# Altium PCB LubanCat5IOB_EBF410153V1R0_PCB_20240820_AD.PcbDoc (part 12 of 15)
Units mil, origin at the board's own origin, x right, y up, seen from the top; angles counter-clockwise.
Board outline 6811.02 x 4055.12 mil, 6 copper layers (TOP, GND02, ART03, ART04, PWR05, BOTTOM), stack 59.279 mil thick; 981 components, 783 nets, 3627 pads, 2669 vias.
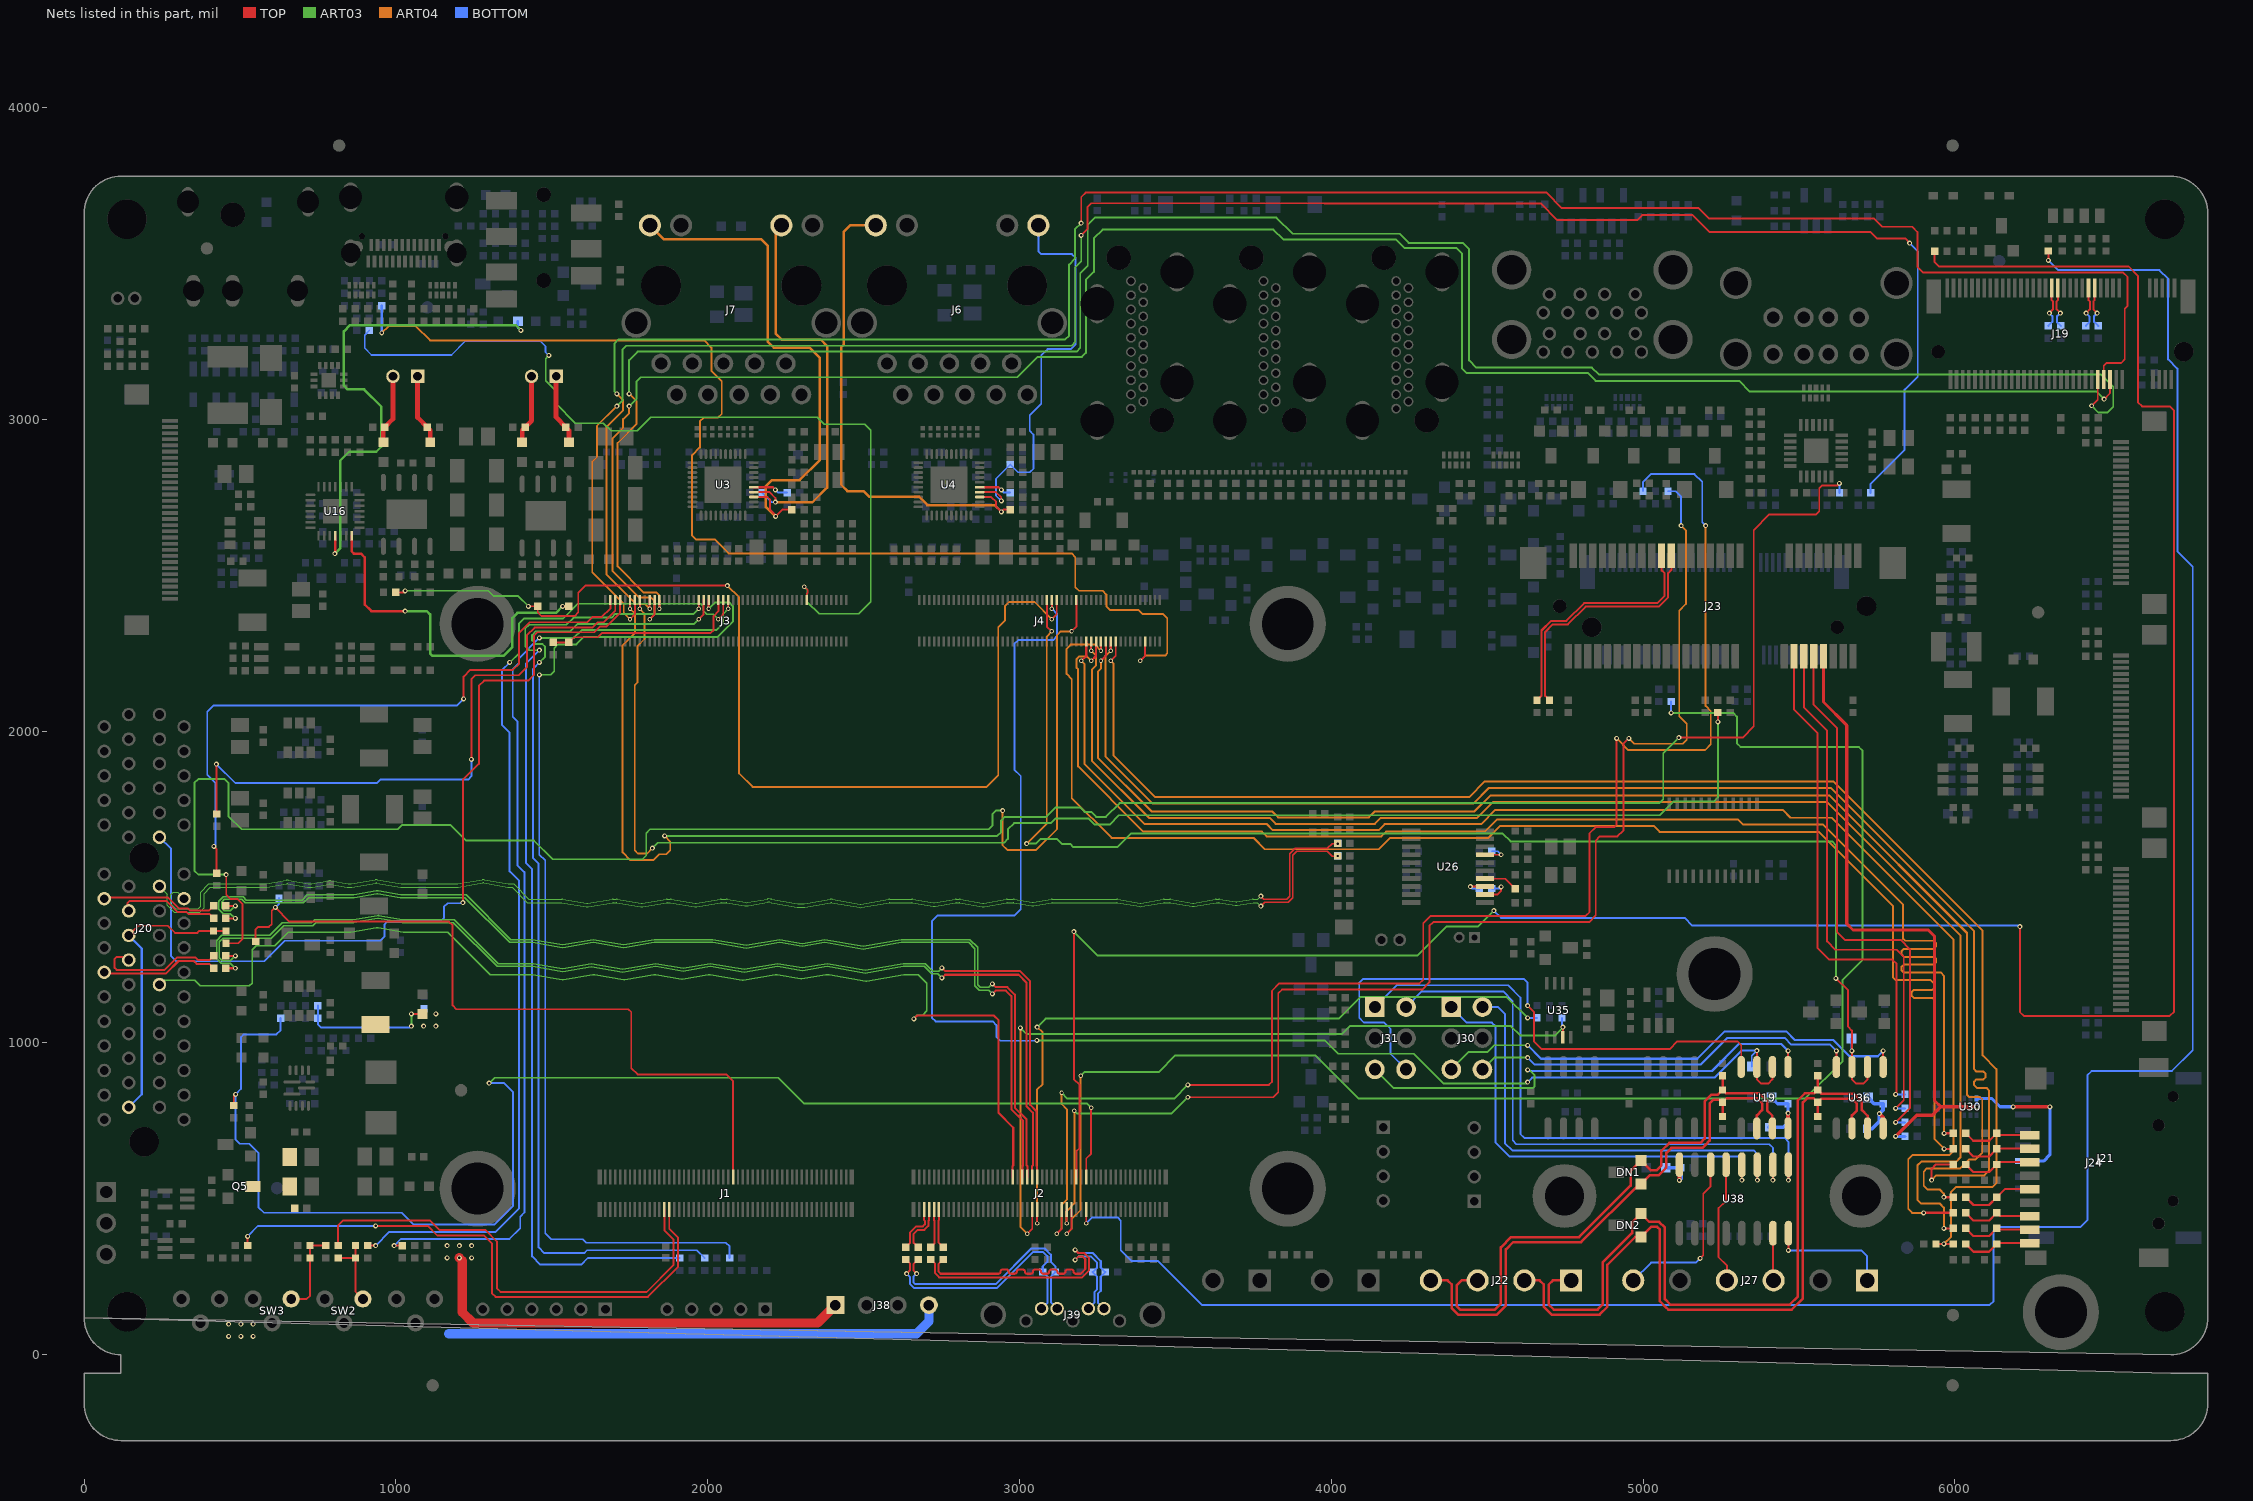
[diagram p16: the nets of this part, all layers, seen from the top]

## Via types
v1: diameter 16, hole 8, TOP to BOTTOM, 2357 vias
v2: diameter 14, hole 8, TOP to BOTTOM, 308 vias
v3: diameter 20, hole 10, TOP to BOTTOM, 4 vias

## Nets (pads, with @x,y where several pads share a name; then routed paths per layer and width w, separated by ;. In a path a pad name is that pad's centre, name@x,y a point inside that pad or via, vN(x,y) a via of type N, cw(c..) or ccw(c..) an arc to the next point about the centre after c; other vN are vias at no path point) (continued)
PCIE30_PORT1_RX1P: J2.39 J20.A21 | length 3642.6
  TOP w6.5: v1(2661,1077.14) 2671.36,1087.5 2918.24,1087.5 2933,1072.74 2933,775 2980.08,727.92 2980.08,606.42 2977.96,604.3 J2.39@2977.96,569.96
  ART03 w4.5: J20.A21@241.73,1187 254.88,1200.15 354.71,1200.15 371.87,1183 530,1183 539,1192 539,1298.67 552.33,1312 611,1312 654,1355 854.22,1355 ccw(c854.22,1364) 855.76,1355.13 936.88,1369.22 cw(c939.98,1351.38) 943.08,1369.22 1024.2,1355.13 ccw(c1025.74,1364) 1025.74,1355 1166,1355 1301.9,1219.1 1435.22,1219.1 cw(c1435.22,1201) 1438.32,1218.83 1533.63,1202.28 ccw(c1535.17,1211.15) 1536.71,1202.28 1632.01,1218.83 cw(c1635.11,1201) 1635.11,1219.1 cw(c1635.11,1201) 1638.21,1218.83 1731.12,1202.7 ccw(c1732.67,1211.62) 1734.22,1202.7 1827.13,1218.83 cw(c1830.22,1201) 1830.22,1219.1 cw(c1830.22,1201) 1833.32,1218.83 1916.18,1204.44 ccw(c1917.72,1213.31) 1919.26,1204.44 2002.12,1218.83 cw(c2005.22,1201) 2005.22,1219.1 cw(c2005.22,1201) 2008.32,1218.83 2111.17,1200.97 ccw(c2112.72,1209.89) 2114.27,1200.97 2217.13,1218.83 cw(c2220.23,1200.99) 2220.22,1219.1 cw(c2220.22,1201) 2223.32,1218.83 2299.22,1205.65 ccw(c2300.76,1214.52) 2302.3,1205.65 2378.2,1218.83 cw(c2381.29,1201) 2381.29,1219.1 2386.73,1219.1 cw(c2386.73,1201) 2389.83,1218.83 2507.61,1198.38 ccw(c2509.16,1207.3) 2510.7,1198.38 2628.47,1218.83 cw(c2631.57,1201) 2631.57,1219.1 2675.9,1219.1 2703.39,1191.61 2703.39,1103.03 2689.06,1088.7 2672.56,1088.7 v1(2661,1077.14)
PCIE30_PORT1_TX0N: C190.1 J2.45 | length 3522.9
  TOP w6.5: C190.1@454.68,1399.37 v1(485,1399.37) ; v1(2913,1189.36) 2923.36,1179 2961.26,1179 2985.5,1154.76 2985.5,791.76 3023.08,754.19 3023.08,606.42 3025.2,604.3 J2.45@3025.2,569.96
  ART03 w4.5: v1(485,1399.37) 469.55,1414.82 446.23,1414.82 431.9,1429.15 431.9,1454.77 446.23,1469.1 509.77,1469.1 520.77,1458.1 699.23,1458.1 716.13,1475 863.22,1475 ccw(c863.22,1484) 864.76,1475.13 937.35,1487.74 cw(c940.45,1469.9) 943.54,1487.74 1016.13,1475.13 ccw(c1017.67,1484) 1017.67,1475 1225,1475 1368.9,1331.1 1438.12,1331.1 1534.81,1314.31 1632.29,1331.24 1730.59,1314.17 1828.1,1331.1 2016.45,1331.1 2123.16,1312.57 2230.66,1331.24 2303.48,1318.6 2376.29,1331.24 2498.71,1309.98 2620.35,1331.1 2840.9,1331.1 2866,1306 2866,1186.8 2875,1177.8 2901.44,1177.8 v1(2913,1189.36)
PCIE30_PORT1_TX0P: C189.1 J2.43 | length 3473.7
  TOP w6.5: C189.1@454.68,1439.37 v1(485,1439.37) ; v1(2913,1157.14) 2923.36,1167.5 2956.5,1167.5 2974,1150 2974,787 3011.58,749.42 3011.58,606.42 3009.45,604.3 J2.43@3009.45,569.96
  ART03 w4.5: v1(485,1439.37) 469.55,1423.92 450,1423.92 441,1432.92 441,1451 450,1460 506,1460 517,1449 703,1449 719.9,1465.9 863.23,1465.9 ccw(c863.23,1484) 866.32,1466.17 938.91,1478.77 cw(c940.45,1469.9) 941.99,1478.77 1014.57,1466.17 ccw(c1017.67,1484) 1017.67,1465.9 1221.23,1465.9 1365.13,1322 1437.33,1322 1534.81,1305.07 1632.29,1322 1730.59,1304.93 1828.89,1322 2015.66,1322 2123.16,1303.34 2230.66,1322 2303.48,1309.36 2376.29,1322 2498.71,1300.74 2621.14,1322 2837.13,1322 2856.9,1302.23 2856.9,1183.03 2871.23,1168.7 2901.44,1168.7 v1(2913,1157.14)
PCIE30_PORT1_TX1N: C192.1 J2.49 | length 3546
  TOP w6.5: C192.1@454.68,1239.37 v1(485,1239.37) ; v1(2751,1240.36) 2761.36,1230 3002,1230 3034,1198 3034,801.26 3054.57,780.69 3054.57,606.42 3056.7,604.3 J2.49@3056.7,569.96
  ART03 w4.5: v1(485,1239.37) 469.55,1254.82 439.33,1254.82 425,1269.15 425,1328 442,1345 596.13,1345 636.13,1385 729.13,1385 739.23,1395.1 862.22,1395.1 ccw(c862.22,1404.1) 863.76,1395.23 939.6,1408.4 cw(c942.7,1390.57) 945.79,1408.4 1021.63,1395.23 ccw(c1023.17,1404.1) 1023.17,1395.1 1187.77,1395.1 1328.77,1254.1 1439.81,1254.1 1535.17,1237.54 1625.98,1253.31 1727.34,1235.71 1834.02,1254.24 1921.53,1239.04 2009.02,1254.24 2116.52,1235.57 2224.02,1254.24 2303.48,1240.44 2382.93,1254.24 2505.35,1232.98 2626.99,1254.1 2697.9,1254.1 2721.9,1230.1 2740.74,1230.1 v1(2751,1240.36)
PCIE30_PORT1_TX1P: C191.1 J2.47 | length 3497.9
  TOP w6.5: C191.1@454.68,1279.37 v1(485,1279.37) ; v1(2751,1208.14) 2761.36,1218.5 2997.24,1218.5 3022.5,1193.24 3022.5,796.5 3043.07,775.93 3043.07,606.42 3040.95,604.3 J2.47@3040.95,569.96
  ART03 w4.5: v1(485,1279.37) 469.55,1263.92 443.1,1263.92 434.1,1272.92 434.1,1324.23 445.77,1335.9 599.9,1335.9 639.9,1375.9 732.9,1375.9 743,1386 862.23,1386 ccw(c862.23,1404.1) 865.32,1386.27 941.16,1399.43 cw(c942.7,1390.57) 944.24,1399.44 1020.07,1386.27 ccw(c1023.17,1404.1) 1023.17,1386 1184,1386 1325,1245 1439.02,1245 1535.17,1228.31 1625.98,1244.07 1727.34,1226.47 1834.02,1245 1921.53,1229.81 2009.02,1245 2116.52,1226.33 2224.02,1245 2303.48,1231.2 2382.93,1245 2505.35,1223.74 2627.78,1245 2694.13,1245 2718.13,1221 2738.14,1221 v1(2751,1208.14)
PCIE30X1_0_CLKREQN_M0: J2.62 R145.1 | length 4343.9
  TOP w6: v2(3151.19,420.89) J2.62@3151.19,465.62 ; v1(3540,825.63) 3813.63,825.63 3830,842 3830,1159.01 3842,1171.01 4292.29,1171.01 4315,1193.71 4315,1375.37 4327,1387.37 4826.97,1387.37 4848.31,1408.71 4848.31,1649 4861.31,1662 4918,1662 4937,1681 4937,1958.85 v1(4954.77,1976.62)
  ART03 w6: v2(3176,782) 3184,774 3488.37,774 v1(3540,825.63)
  ART04 w6: v2(3151.19,420.89) 3151.19,460.19 3176,485 v2(3176,782) ; v1(4954.77,1976.62) 4972.02,1959.37 5127.4,1959.37 5140,1971.97 5140,2023.37 5116,2047.37 5116,2386.37 5137.2,2407.57 5137.2,2643.85 v1(5122.05,2659)
  BOTTOM w6: R145.1@5080,2769.05 5105.32,2769.05 5122.05,2752.32 v1(5122.05,2659)
PCIE30X1_0_PERSTN_M0: J2.64 R144.2 | length 4960.3
  TOP w6: v2(3151.19,387.89) 3166.93,403.63 J2.64@3166.93,465.62
  ART03 w6: v2(3196,894) 3208.37,906.37 3446.37,906.37 3500,960 3949,960 4087,822 5521,822 5640,941 5640,1202.65 5704.32,1266.97 5704.32,1937 5692.32,1949 5313,1949 5301,1961 5301,2046.37 5289,2058.37 v1(5090,2058.37)
  ART04 w6: v2(3151.19,387.89) 3167.68,404.38 3167.68,435.68 3196,464 v2(3196,894)
  BOTTOM w6: v1(5090,2058.37) R144.2@5090,2094.69
PCIE30X1_0_WAKEN_M0: J2.60 R148.1 | length 4829.4
  TOP w6: v2(3119.69,387.89) 3135.44,403.63 J2.60@3135.44,465.62 ; v1(3540,865) 3800,865 3810,875 3810,1167.29 3833.72,1191.01 4283,1191.01 4295,1203.01 4295,1383.65 4318.72,1407.37 4816.31,1407.37 4828.31,1419.37 4828.31,1672.31 4848,1692 4907,1692 4915.4,1700.4 v1(4915.4,1976.62)
  ART03 w6: v2(3135,840) 3153.63,821.37 3496.37,821.37 v1(3540,865)
  ART04 w6: v2(3119.69,387.89) 3134.69,402.89 3134.69,479.69 3152,497 3152,787 3135,804 v2(3135,840) ; v1(4915.4,1976.62) 4952.95,1939.07 5198.7,1939.07 5217,1957.37 5217,2064.37 5200.79,2080.58 v1(5200.79,2659)
  BOTTOM w6: R148.1@5000,2769.05 5000,2799.37 5025,2824.37 5165,2824.37 5190,2799.37 5190,2669.79 v1(5200.79,2659)
PCIE30X1_1_CLKREQN_M1: J3.12 R266.1 | length 5874.7
  TOP w6: v2(1750.89,2392) J3.12@1750.89,2420.74 ; v1(5115,1979.37) 5319.37,1979.37 5355,2015 5355,2644.63 5405.37,2695 5555,2695 5565,2705 5565,2779.37 5573.23,2787.6 5623.23,2787.6 v1(5630,2794.37)
  ART03 w6: v1(1862,1663.74) 2928.74,1663.74 2941,1676 2941,1713 2953,1725 3086,1725 3116,1755 3195,1755 3209,1741 3230,1741 3246,1725 3277,1725 3321,1769 5052,1769 5065,1782 5065,1929.37 v1(5115,1979.37)
  ART04 w6: v2(1750.89,2392) 1767,2375.89 1767,2315 1727,2275 1727,1611 1752,1586 1825,1586 1844,1605 1867,1605 1880,1618 1880,1645.74 v1(1862,1663.74)
  BOTTOM w6: R266.1@5630,2764.05 v1(5630,2794.37)
PCIE30X1_1_PERSTN_M1: J3.16 R268.2 | length 4681.5
  TOP w6: v2(1782.39,2392) J3.16@1782.39,2420.74 ; v1(5240,2029.37) R268.2@5240,2059.69
  ART03 w6: v1(1822.63,1624.37) 1840.26,1642 2951,1642 2963,1654 2963,1685 2983,1705 3101,1705 3115.17,1719.17 3221.83,1719.17 3241,1700 3289,1700 3319,1730 5053,1730 5097,1774 5227,1774 5240,1787 v1(5240,2029.37)
  ART04 w6: v2(1782.39,2392) 1797.39,2377 1797.39,2295.39 1774.85,2272.85 1774.85,2155.85 1766.26,2147.26 1766.26,1617.33 1776.22,1607.37 1805.63,1607.37 v1(1822.63,1624.37)
PCIE30X1_1_WAKEN_M1: J3.14 R265.1 | length 6516.8
  TOP w6: v2(1750.89,2359) 1766.64,2374.75 J3.14@1766.64,2420.74 ; v1(3198,3589.63) 3218,3609.63 3218,3680 3231,3693 3977.33,3693 3977.96,3692.37 4671.63,3692.37 4725,3639 4981,3639 4997,3655 5159,3655 5213,3601 5729,3601 5750,3580 5840.37,3580 v1(5855,3565.37)
  ART03 w6: v1(1708.74,3042.48) 1727,3060.74 1727,3224 1739,3236 3167,3236 3179,3248 3179,3487.72 3198,3506.72 v1(3198,3589.63)
  ART04 w6: v1(1708.74,3042.48) 1645,2978.74 1645,2878.79 1630,2863.79 1630,2510 1730.89,2409.11 1730.89,2379.01 v2(1750.89,2359)
  BOTTOM w6: R265.1@5730,2764.05 5730,2793.37 5839,2902.37 5839,3095 5881,3137 5881,3539.37 v1(5855,3565.37)
PCIE30X2_CLKREQN_M1: J3.4 R248.1 | length 2093
  TOP w6: v1(416.38,1630) 425,1621.38 R248.1@425,1544.05 ; v1(1217,2103) 1217,2175 1238,2196 1375,2196 1395,2216 1395,2315 1429,2349 1614,2349 1631,2366 1661,2366 1687.9,2392.9 J3.4@1687.9,2420.74
  BOTTOM w6: v1(416.38,1630) 422,1635.62 422,1832.37 395,1859.37 395,2061.98 415.2,2082.18 1196.18,2082.18 v1(1217,2103)
PCIE30X2_PERSTN_M1: J3.8 J20.A11 | length 2842.2
  TOP w6: v1(1215,1450) 1215,1844 1266,1895 1266,2145 1283,2162 1425,2162 1443,2180 1443,2306 1454,2317 1636,2317 1654.25,2335.25 1675,2335.25 1719.39,2379.65 J3.8@1719.39,2420.74
  BOTTOM w6: J20.A11@241.73,1659.44 279,1622.17 279,1278.37 295.4,1261.97 577.97,1261.97 643.37,1327.37 949.4,1327.37 963,1340.97 963,1379.37 973,1389.37 1143,1389.37 1154,1400.37 1154,1436 1166,1448 1213,1448 v1(1215,1450)
PCIE30X2_PRSNTN: J4.66 R137.1 | length 4695.9
  TOP w6: R137.1@455,1319.69 495.02,1319.69 508.62,1333.29 508.62,1444.96 492.21,1461.37 470,1461.37 455.75,1475.62 v1(455.75,1540) ; v2(3166.94,2319.63) 3182.69,2335.38 J4.66@3182.69,2420.74
  ART03 w6: v1(455.75,1540) 366,1540 354,1552 354,1834 366,1846 451,1846 463,1834 463,1727 505,1685 1006,1685 1020,1699 1175,1699 1225,1649 1443,1649 1503,1589 1791,1589 1803,1601 1803,1673 1815,1685 2901,1685 2913,1697 2913,1734 2924,1745 v1(2945.63,1745)
  ART04 w6: v1(2945.63,1745) 2945.63,1634.37 2961,1619 3054,1619 3120.44,1685.44 3120.44,2307.44 3132.63,2319.63 v2(3166.94,2319.63)
PCIE30X2_WAKEN_M1: J3.6 R247.1 | length 1970.9
  TOP w6: v1(424.26,1894.37) 425,1893.63 R247.1@425,1734.05 ; v1(1242,1909) 1242,2166 1255,2179 1394,2179 1420,2205 1420,2307 1445,2332 1630,2332 1647.25,2349.25 1666.52,2349.25 1703.65,2386.37 J3.6@1703.65,2420.74
  BOTTOM w6: v1(424.26,1894.37) 485.6,1833.03 938.66,1833.03 950.26,1844.63 1231.63,1844.63 1242,1855 v1(1242,1909)
PCIE30X4_CLKREQN_M1: J3.20 J19.52 | length 6842.7
  TOP w6: v2(1813.88,2392) J3.20@1813.88,2420.74 ; v1(3198,3629) 3198,3713 3211.87,3726.87 4690.5,3726.87 4740,3677.37 5178,3677.37 5211,3644.37 5740,3644.37 5767,3617.37 5863.4,3617.37 5880,3600.77 5880,3489.37 5899,3470.37 6540,3470.37 6554,3456.37 6554,3363.51 6545,3354.51 6545,3192 6533,3180 6486,3180 6477.51,3171.51 6477.51,3128.88 J19.52@6478.04,3128.35
  ART03 w6: v1(1708.74,3081.85) 1701,3089.59 1701,3243 1714,3256 3147,3256 3159,3268 3159,3496 3178,3515 3178,3609 v1(3198,3629)
  ART04 w6: v1(1708.74,3081.85) 1728,3062.59 1728,3028 1675,2975 1675,2503 1770,2408 1797.88,2408 v2(1813.88,2392)
PCIE30X4_PERSTN_M1: J3.24 J19.50 | length 6785.7
  TOP w6: v2(1845.38,2392) J3.24@1845.38,2420.74 ; v1(6438.67,3043.47) 6458.35,3063.15 J19.50@6458.35,3128.35
  ART03 w6: v1(1748.11,3081.85) 1748.11,3190.11 1775,3217 3183,3217 3195,3229 3195,3468 3219,3492 3219,3624 3242,3647 3824,3647 3876,3595 4219,3595 4248,3566 4422,3566 4442,3546 4442,3189 4465,3166 4836,3166 4858,3144 6468,3144 6508,3104 6508,3039.97 6489.4,3021.37 6460.77,3021.37 v1(6438.67,3043.47)
  ART04 w6: v1(1748.11,3081.85) 1772,3057.96 1772,2985 1711,2924 1711,2528 1794,2445 1835.38,2445 1845.38,2435 v2(1845.38,2392)
PCIE30X4_WAKEN_M1: J3.22 J19.54 | length 6569.3
  TOP w6: v2(1813.88,2359) 1829.63,2374.75 J3.22@1829.63,2420.74 ; v1(6479,3065) 6497.72,3083.72 J19.54@6497.72,3128.35
  ART03 w6: v1(1748.11,3042.48) 1772,3066.37 1772,3122 1785,3135 2993,3135 3058,3200 3200,3200 3213,3213 3213,3447 3239,3473 3239,3581 3266.52,3608.52 3814.48,3608.52 3846,3577 4207,3577 4235,3549 4402,3549 4419,3532 4419,3163 4433,3149 4822,3149 4847.89,3123.11 5308.11,3123.11 5342.22,3089 6455,3089 v1(6479,3065)
  ART04 w6: v1(1748.11,3042.48) 1748.11,3022.11 1748,3022 1748,3019.72 1729,3000.72 1729,2973 1695,2939 1695,2513 1779,2429 1817,2429 1830,2416 1830,2375.12 v2(1813.88,2359)
PCIEX4_PETN0: C190.2 J20.B15 | length 328.2
  TOP w6.5: J20.B15@143.3,1423.22 139,1427.53 139,1447.87 145.5,1454.37 265,1454.37 299.18,1420.19 327.84,1420.19 334.41,1413.62 401.07,1413.62 C190.2@415.32,1399.37
PCIEX4_PETN1: C192.2 J20.B20 | length 378.5
  TOP w6.5: J20.B20@64.56,1226.37 68.22,1222.71 262.91,1222.71 302.9,1262.71 351.66,1262.71 360.75,1253.62 401.07,1253.62 C192.2@415.32,1239.37
PCIEX4_PETP0: C189.2 J20.B14 | length 374.9
  TOP w6.5: J20.B14@64.56,1462.59 67.84,1465.87 269.76,1465.87 303.94,1431.69 332.6,1431.69 339.17,1425.12 401.07,1425.12 C189.2@415.32,1439.37
PCIEX4_PETP1: C191.2 J20.B19 | length 427.9
  TOP w6.5: J20.B19@143.3,1265.74 133.05,1276 104.18,1276 97.68,1269.5 97.68,1240.71 104.18,1234.21 258.14,1234.21 298.14,1274.21 356.42,1274.21 365.51,1265.12 401.07,1265.12 C191.2@415.32,1279.37
PCIEX4_PRSNTN: J20.B17 J20.B31 R137.2 R328.2 | length 922.3
  TOP w6: J20.B17@143.3,1344.48 174.36,1375.54 268.83,1375.54 291.57,1352.8 363.43,1352.8 369.68,1359.05 R328.2@415,1359.05 R137.2@455,1359.05
  BOTTOM w6.8: J20.B31@143.3,793.3 185,835 185,1302.79 J20.B17@143.3,1344.48
PCIEX4_PWR_EN: J1.53 R251.2 R256.1 | length 2453.4
  TOP w6: R256.1@550.32,1325 550.32,1364.32 558,1372 593,1372 602,1381 602,1423.14 v1(613.23,1434.37) 658.6,1389 1170,1389 1182,1377 1182,1120 1194,1108 1746,1108 1755,1099 1755,919 1775,899 2060,899 2081.59,877.41 J1.53@2081.59,569.96
  BOTTOM w6: v1(613.23,1434.37) 625.32,1446.46 R251.2@625.32,1464.37
PCIEX4_REF_CLKN: J20.A14 R239.2 R240.1 | length 4108.8
  TOP w4.5: v1(3774,1470.95) 3783.95,1461 3857.5,1461 3866.5,1470 3866.5,1605.94 3884.68,1624.12 3987.34,1624.12 4002.59,1639.37 v1(4020.32,1639.37)
  ART03 w4: J20.A14@320.47,1462.59 300.06,1483 286,1483 278,1475 278,1446 294,1430 366,1430 374,1438 374,1483.56 400.44,1510 582.31,1510 ccw(c582.31,1518) 583.68,1510.12 648.41,1521.36 cw(c651.66,1502.64) 654.91,1521.36 719.63,1510.12 ccw(c721,1518) 721,1510 728.31,1510 ccw(c728.31,1518) 729.68,1510.12 784.9,1519.71 cw(c788.16,1500.99) 791.41,1519.71 846.63,1510.12 ccw(c848,1518) 848,1510 855.31,1510 ccw(c855.31,1518) 856.68,1510.12 934.02,1523.55 cw(c937.27,1504.83) 940.52,1523.55 1017.87,1510.12 ccw(c1019.23,1518) 1019.23,1510 1197.31,1510 ccw(c1197.31,1518) 1198.68,1510.12 1276.68,1523.66 cw(c1279.93,1504.94) 1283.18,1523.66 1361.19,1510.12 ccw(c1362.56,1518) 1362.56,1510 1377.56,1510 1426.56,1461 1531.31,1461 cw(c1531.31,1442) 1534.56,1460.72 1612.57,1447.17 ccw(c1613.93,1455.06) 1615.3,1447.18 1693.31,1460.72 cw(c1696.56,1442) 1696.56,1461 1706.31,1461 cw(c1706.31,1442) 1709.56,1460.72 1787.13,1447.25 ccw(c1788.5,1455.13) 1789.87,1447.25 1867.44,1460.72 cw(c1870.69,1442) 1870.69,1461 1879.31,1461 cw(c1879.31,1442) 1882.56,1460.72 1959.88,1447.29 ccw(c1961.25,1455.18) 1962.62,1447.29 2039.93,1460.72 cw(c2043.18,1442) 2043.18,1461 2059.31,1461 cw(c2059.31,1442) 2062.56,1460.72 2121.37,1450.51 ccw(c2124.78,1470.12) 2128.18,1450.51 2190.99,1461.41 cw(c2194.24,1442.69) 2194.24,1461.69 cw(c2194.25,1395.58) 2205.56,1460.72 2289.02,1446.23 ccw(c2299.31,1505.49) 2309.6,1446.23 2393.06,1460.72 cw(c2396.31,1442) 2396.31,1461 cw(c2396.31,1442) 2399.56,1460.72 2488.97,1445.19 ccw(c2490.34,1453.08) 2491.71,1445.19 2581.12,1460.72 cw(c2584.37,1442) 2584.37,1461 2654.31,1461 cw(c2654.31,1442) 2657.56,1460.72 2724.64,1449.07 ccw(c2726.01,1456.95) 2727.38,1449.07 2794.46,1460.72 cw(c2797.71,1442) 2797.71,1461 2807.31,1461 cw(c2807.31,1442) 2810.56,1460.72 2882.64,1448.2 ccw(c2884.01,1456.09) 2885.38,1448.2 2957.46,1460.72 cw(c2960.71,1442) 2960.71,1461 2980.31,1461 cw(c2980.31,1442) 2983.56,1460.72 3041.27,1450.7 ccw(c3042.63,1458.58) 3044,1450.7 3101.71,1460.72 cw(c3104.96,1442) 3104.96,1461 3312.31,1461 cw(c3312.31,1442) 3315.56,1460.72 3387.04,1448.31 ccw(c3388.41,1456.19) 3389.78,1448.31 3461.26,1460.72 cw(c3464.51,1442) 3464.51,1461 3482.31,1461 cw(c3482.31,1442) 3485.56,1460.72 3555.68,1448.55 ccw(c3557.04,1456.43) 3558.41,1448.55 3628.53,1460.72 cw(c3631.78,1442) 3631.78,1461 3639.31,1461 cw(c3639.31,1442) 3642.56,1460.72 3693.6,1451.86 ccw(c3694.97,1459.74) 3696.33,1451.86 3747.37,1460.72 cw(c3750.62,1442) 3750.62,1461 3764.05,1461 v1(3774,1470.95)
PCIEX4_REF_CLKP: J20.A13 R238.2 R241.1 | length 4111.9
  TOP w4.5: v1(3774,1438.79) 3786.71,1451.5 3861.44,1451.5 3876,1466.06 3876,1602 3888.62,1614.62 3987.34,1614.62 4002.59,1599.37 v1(4020.32,1599.37)
  ART03 w4: J20.A13@241.73,1501.96 267,1476.69 267,1441.44 289.44,1419 370.56,1419 385,1433.44 385,1479 405,1499 582.31,1499 ccw(c582.31,1518) 585.56,1499.28 650.29,1510.52 cw(c651.66,1502.64) 653.02,1510.52 717.75,1499.28 ccw(c721,1518) 721,1499 728.31,1499 ccw(c728.31,1518) 731.56,1499.28 786.79,1508.87 cw(c788.16,1500.99) 789.52,1508.87 844.75,1499.28 ccw(c848,1518) 848,1499 855.31,1499 ccw(c855.31,1518) 858.56,1499.28 935.9,1512.71 cw(c937.27,1504.83) 938.64,1512.71 1015.98,1499.28 ccw(c1019.23,1518) 1019.23,1499 1197.31,1499 ccw(c1197.31,1518) 1200.56,1499.28 1278.57,1512.83 ; 1278.57,1512.83 cw(c1279.93,1504.94) 1281.3,1512.83 ; 1281.3,1512.83 1359.31,1499.28 ccw(c1362.56,1518) 1362.56,1499 1373,1499 1422,1450 1531.31,1450 cw(c1531.31,1442) 1532.68,1449.88 1610.68,1436.34 ccw(c1613.93,1455.06) 1617.18,1436.34 1695.19,1449.88 cw(c1696.56,1442) 1696.56,1450 1706.31,1450 cw(c1706.31,1442) 1707.68,1449.88 1785.25,1436.41 ccw(c1788.5,1455.13) 1791.75,1436.41 1869.33,1449.88 cw(c1870.7,1442) 1870.7,1450 1879.31,1450 cw(c1879.31,1442) 1880.68,1449.88 1958,1436.46 ccw(c1961.25,1455.18) 1964.5,1436.46 2041.82,1449.88 cw(c2043.18,1442) 2043.18,1450 2059.31,1450 cw(c2059.31,1442) 2060.68,1449.88 2119.49,1439.67 ccw(c2124.78,1470.12) 2130.06,1439.67 2192.88,1450.58 cw(c2194.24,1442.69) 2194.24,1450.69 cw(c2194.25,1395.58) 2203.68,1449.88 2287.14,1435.39 ccw(c2299.31,1505.49) 2311.48,1435.39 2394.94,1449.88 cw(c2396.31,1442) 2396.31,1450 cw(c2396.31,1442) 2397.68,1449.88 2487.09,1434.36 ccw(c2490.34,1453.08) 2493.59,1434.36 2583.01,1449.88 cw(c2584.37,1442) 2584.37,1450 2654.31,1450 cw(c2654.31,1442) 2655.68,1449.88 2722.76,1438.23 ccw(c2726.01,1456.95) 2729.26,1438.23 2796.35,1449.88 cw(c2797.72,1442) 2797.71,1450 2807.31,1450 cw(c2807.31,1442) 2808.68,1449.88 2880.76,1437.37 ccw(c2884.01,1456.09) 2887.26,1437.37 2959.34,1449.88 cw(c2960.71,1442) 2960.71,1450 2980.31,1450 cw(c2980.31,1442) 2981.68,1449.88 3039.38,1439.86 ccw(c3042.63,1458.58) 3045.88,1439.86 3103.59,1449.88 cw(c3104.96,1442) 3104.96,1450 3312.31,1450 cw(c3312.31,1442) 3313.68,1449.88 3385.16,1437.47 ccw(c3388.41,1456.19) 3391.66,1437.47 3463.15,1449.88 cw(c3464.51,1442) 3464.51,1450 3482.31,1450 cw(c3482.31,1442) 3483.68,1449.88 3553.79,1437.71 ccw(c3557.04,1456.43) 3560.29,1437.71 3630.41,1449.88 cw(c3631.78,1442) 3631.78,1450 3639.31,1450 cw(c3639.31,1442) 3640.68,1449.88 3691.72,1441.02 ccw(c3694.97,1459.74) 3698.21,1441.02 3749.25,1449.88 cw(c3750.62,1442) 3750.62,1450 3762.79,1450 v1(3774,1438.79)
PDN: R224.2 U26.7 | length 86.6
  TOP w6: U26.7@4493.11,1603.39 v1(4545,1603.39)
  BOTTOM w6: R224.2@4515,1614.68 4533.71,1614.68 v1(4545,1603.39)
PE_TXN: C214.2 J23.31 | length 802.6
  TOP w6.5: C214.2@4700,2099.05 4685.75,2113.3 4685.75,2317.75 4710,2342 4759,2342 4816,2399 5050,2399 5080.56,2429.55 5080.56,2506.55 5090.55,2516.55 J23.31@5090.55,2562.26
PE_TXP: C215.2 J23.33 | length 802.6
  TOP w6.5: C215.2@4660,2099.05 4674.25,2113.3 4674.25,2322.51 4705.24,2353.5 4754.24,2353.5 4811.24,2410.5 5045.24,2410.5 5069.06,2434.32 5069.06,2506.55 5059.06,2516.55 J23.33@5059.06,2562.26
PETN0: C177.2 J19.47 | length 137.9
  TOP w6.5: v1(6421.03,3340.62) 6432.92,3352.5 6432.92,3378.29 6428.82,3382.39 J19.47@6428.82,3421.65
  BOTTOM w6.5: C177.2@6420,3299.68 6431.79,3311.47 6431.79,3329.86 v1(6421.03,3340.62)
PETN1: C175.2 J19.35 | length 137.9
  TOP w6.5: v1(6302.92,3340.62) 6314.81,3352.5 6314.81,3378.29 6310.71,3382.39 J19.35@6310.71,3421.65
  BOTTOM w6.5: C175.2@6300,3299.68 6312.74,3312.42 6312.74,3330.8 v1(6302.92,3340.62)
PETP0: C178.2 J19.49 | length 137.9
  TOP w6.5: J19.49@6448.51,3421.65 6448.51,3382.39 6444.42,3378.29 6444.42,3352.5 v1(6456.3,3340.62)
  BOTTOM w6.5: v1(6456.3,3340.62) 6446.87,3331.19 6446.87,3312.81 C178.2@6460,3299.68
PETP1: C176.2 J19.37 | length 137.9
  TOP w6.5: J19.37@6330.4,3421.65 6330.4,3382.39 6326.31,3378.29 6326.31,3352.5 v1(6338.19,3340.62)
  BOTTOM w6.5: v1(6338.19,3340.62) 6327.82,3330.25 6327.82,3311.86 C176.2@6340,3299.68
PHY0_CLKOUT125: R37.2 U4.35 | length 104.8
  TOP w6.8: U4.35@2872.43,2782.13 2933.1,2782.13 v1(2941.8,2773.43)
  BOTTOM w6.8: v1(2941.8,2773.43) 2950.55,2764.68 R37.2@2970,2764.68
PHY0_LED1: J6.14 R44.1 U4.33 | length 1604.5
  TOP w6: U4.33@2872.43,2750.63 2909.37,2750.63 2925,2735 2925,2720.23 v1(2941.8,2703.43) 2948.69,2710.32 R44.1@2970,2710.32
  ART04 w8: J6.14@2539.17,3622.06 2457,3622.06 2437,3602.06 2437,3240 2428,3231 2428,2790 2448,2770 2500,2770 2518,2752 2678,2752 2705,2725 2920.23,2725 v1(2941.8,2703.43)
PHY0_LED2: J6.11 R43.1 U4.34 | length 1316.6
  TOP w6: U4.34@2872.43,2766.38 2924.8,2766.38 2941.8,2749.39 v1(2941.8,2738.43)
  BOTTOM w6: v1(2941.8,2738.43) 2924.76,2755.47 2924.76,2809.44 R43.1@2970.32,2855 2995.32,2830 3033,2830 3045,2842 3045,2951 3032.91,2963.09 3032.91,3012.91 3070,3050 3070,3205 3090,3225 3165,3225 3180,3240 3180,3518 3168,3530 3070,3530 3060.83,3539.17 J6.11@3060.83,3622.06
PHY1_CLKOUT125: R67.2 U3.35 | length 114.2
  TOP w6.8: U3.35@2148.02,2782.13 2208.69,2782.13 v1(2217.39,2773.43)
  BOTTOM w6.8: v1(2217.39,2773.43) 2226.14,2764.68 R67.2@2255,2764.68
PHY1_LED1: J7.14 R72.1 U3.33 | length 1724.1
  TOP w6: U3.33@2148.02,2750.63 2191.9,2750.63 2200.39,2742.14 2200.39,2710.41 2218,2692.8 v1(2218,2688.61) 2239.71,2710.32 R72.1@2270,2710.32
  ART04 w8: J7.14@1814.76,3622.06 1859.82,3577 2172,3577 2192,3557 2192,3250 2212,3230 2326,3230 2360,3196 2360,2870 2295,2805 2206,2805 2186,2785 2186,2720.61 v1(2218,2688.61)
PHY1_LED2: J7.12 R73.1 U3.34 | length 1321.5
  TOP w6: U3.34@2148.02,2766.38 2198.62,2766.38 2217.39,2747.61 v1(2217.39,2734.06)
  ART04 w8: v1(2217.39,2734.06) 2336.06,2734.06 2383,2781 2383,3235 2363,3255 2238,3255 2218,3275 2218,3603.64 J7.12@2236.42,3622.06
  BOTTOM w6: R73.1@2174.68,2765 2205.62,2734.06 v1(2217.39,2734.06)
PWM7_IR_M0: J2.70 R110.1 | length 7461.4
  TOP w6: v2(3214.18,420.89) J2.70@3214.18,465.62 ; v1(6300,3509.37) R110.1@6300,3539.69
  BOTTOM w6: v2(3214.18,420.89) 3233.29,440 3315,440 3325,430 3325,335 3360,300 3445,300 3585.23,159.77 6112.2,159.77 6124.2,171.77 6124.2,397.37 6136.2,409.37 6403,409.37 6425,431.37 6425,896.37 6438.4,909.77 6696.4,909.77 6762.94,976.31 6762.94,2527.43 6714,2576.37 6714,3162.37 6684,3192.37 6684,3450.37 6656,3478.37 6331,3478.37 v1(6300,3509.37)
PWR_ON: J1.28 R19.2 | length 1846.9
  TOP w6: R19.2@524.68,350 v1(524.68,379.68) ; v1(935,412.77) 1102.86,412.77 1133.49,382.14 1282.86,382.14 1308,357 1308,197.25 1320,185.25 1808.25,185.25 1905,282 1905,375 1876.87,403.13 J1.28@1876.87,465.62
  BOTTOM w6: v1(524.68,379.68) 557.77,412.77 v1(935,412.77)
RECOVERY: C5.1 D3.2 R2.1 SW2.2 | length 236.7
  TOP w6: C5.1@814.68,310 D3.2@870.32,310 ; R2.1@870.32,350 D3.2@870.32,310 ; SW2.2@894.14,178.81 870.32,202.64 D3.2@870.32,310
RECOVERY_KEY: J3.50 R2.2 | length 3219.6
  TOP w6: R2.2@909.68,350 v1(935,350) ; v2(2034.36,2359) 2050.1,2374.75 J3.50@2050.1,2420.74
  ART03 w6: v1(1365,2220) 1395,2250 1395,2346 1410,2361 1536,2361 1583.52,2408.52 1977.48,2408.52 1985.96,2400.04 1985.96,2385.72 1997,2374.68 2018.68,2374.68 v2(2034.36,2359)
  BOTTOM w6: v1(935,350) 979,394 1320,394 1395,469 1395,1520 1365,1550 1365,1995 1340,2020 1340,2195 v1(1365,2220)
RESETN: J1.26 R5.2 | length 1555.3
  TOP w6: R5.2@814.68,350 814.68,414.68 830,430 1110,430 1140.63,399.37 1287.63,399.37 1324,363 1324,213 1336,201 1804,201 1890,287 1890,370 1861.12,398.88 J1.26@1861.12,465.62
ROUT1: C287.1 U16.11 | length 1579.6
  TOP w8: v1(804.37,2569.17) 805,2569.8 U16.11@805,2626.26
  ART03 w8: v1(804.37,2569.17) 821,2585.8 821,2867 850,2896 937,2896 953,2912 953,3041 898,3096 845,3096 833,3108 833,3282.06 852.94,3302 1384.37,3302 v1(1401,3285.37)
  BOTTOM w8: C287.1@1391.5,3314.37 1391.5,3294.87 v1(1401,3285.37)
ROUT2: C308.1 U16.14 | length 1167.5
  TOP w8: U16.14@858.15,2626.26 858.15,2576.85 865.63,2569.37 887.74,2569.37 900.21,2556.9 900.21,2406 921.21,2385 v1(1030,2385) ; v1(1535,2400.32) C308.1@1555,2400.32
  ART03 w8: v1(1030,2385) 1099,2385 1110,2374 1110,2249 1118,2241 1345,2241 1374,2270 1374,2363 1390,2379 1513.68,2379 v1(1535,2400.32)
RS232_3V3: C244.1 L24.1 U38.16 | length 140.9
  TOP w12: v1(5116.57,559.37) 5116.78,559.57 U38.16@5116.78,609.17
  BOTTOM w12: L24.1@5073.07,599.37 C244.1@5121.9,599.37 5121.9,564.69 v1(5116.57,559.37)
RS232_R1IN: J27.4 U38.13 | length 392.2
  TOP w6: U38.13@5266.37,609.17 5266.37,494.37 5242,470 5242,313 5268.74,286.26 J27.4@5268.74,238.19
RS232_R1OUT: J30.1 U38.12 | length 1467
  TOP w6: v1(5316.78,559.57) U38.12@5316.78,609.17
  BOTTOM w6: J30.1@4385,1115 4435,1065 4515,1065 4527,1053 4527,680.14 4572.15,635 5304.78,635 5316.78,623 v1(5316.78,559.57)
RS232_R2IN: J27.1 U38.8 | length 392.7
  TOP w6: v1(5466.37,334.57) U38.8@5466.37,389.57
  BOTTOM w6: v1(5466.37,334.57) 5699.8,334.57 5718.74,315.63 J27.1@5718.74,238.19
RS232_R2OUT: J31.1 U38.9 | length 1992.9
  TOP w6: v1(5466.37,559.57) U38.9@5466.37,609.17
  BOTTOM w6: J31.1@4140,1115 4210,1185 4567,1185 4607,1145 4607,707 4619,695 5454.37,695 5466.37,683 v1(5466.37,559.57)
RS232_T1IN: J30.2 U38.11 | length 1452.8
  TOP w6: v1(5366.37,559.57) U38.11@5366.37,609.17
  BOTTOM w6: J30.2@4485,1115 4535,1115 4557,1093 4557,678.43 4580.43,655 5354.37,655 5366.37,643 v1(5366.37,559.57)
RS232_T1OUT: J27.6 U38.14 | length 557.8
  TOP w6: v1(5183,309) 5193,319 5193,516.59 5216.78,540.37 U38.14@5216.78,609.17
  BOTTOM w6: J27.6@4968.74,238.19 5025.75,295.2 5169.2,295.2 v1(5183,309)
RS232_T2IN: J31.2 U38.10 | length 1820.3
  TOP w6: v1(5416.78,559.57) U38.10@5416.78,609.17
  BOTTOM w6: J31.2@4240,1115 4290,1165 4551,1165 4582,1134 4582,687 4594,675 5404.77,675 5416.78,663 v1(5416.78,559.57)
RS232_T2OUT: J27.3 U38.7 | length 152.2
  TOP w6: U38.7@5416.78,389.57 5416.78,240.15 J27.3@5418.74,238.19
RS485_1_3V3: C242.1 D58.2 L22.2 U36.8 | length 220
  TOP w12: v1(5758,773) 5770,761 U36.8@5770,725.95
  BOTTOM w12: D58.2@5717.95,724.37 5734,724.37 5758,748.37 v1(5758,773) 5770,785 C242.1@5770,804.69 5741.18,804.69 L22.2@5721.5,824.37
RS485_1_A: DN2.1 J22.2 R287.1 R288.2 U36.6 | length 2391.9
  TOP w8: J22.2@4619.37,238.19 4668.4,238.19 4680.8,225.79 4680.8,154.51 4706.94,128.37 4860.63,128.37 4886,153.74 4886,288.37 4975.13,377.5 DN2.1@4993.5,377.5 5026,410 5045,410 5054,401 5054,171.37 5072,153.37 5081.37,144 5476.63,144 5512.41,179.78 5512.41,809.27 5525.31,822.17 5547.52,822.17 R288.2@5560,809.69 ; R287.1@5560,764.05 R288.2@5560,809.69 ; U36.6@5670,725.95 5670,767.37 5685.8,783.17 5685.8,805.87 5670.5,821.17 5571.48,821.17 R288.2@5560,809.69
RS485_1_B: DN2.2 J22.1 R288.1 R292.1 U36.7 | length 2444.5
  TOP w8: J22.1@4769.37,238.19 4710.82,238.19 4696.8,224.17 4696.8,161.13 4713.56,144.37 4854,144.37 4870,160.37 4870,295 4965,390 4965,424 DN2.2@4993.5,452.5 5020,426 5051.63,426 5070,407.63 5070,178 5088,160 5470,160 5496.41,186.41 5496.41,815.9 5518.68,838.17 5549.12,838.17 R288.1@5560,849.05 ; R292.1@5560,894.69 R288.1@5560,849.05 ; U36.7@5720,725.95 5720,766.37 5701.8,784.57 5701.8,812.5 5677.13,837.17 5571.88,837.17 R288.1@5560,849.05
RS485_1_DIR: J4.54 R289.1 U36.2 U36.3 | length 4382
  TOP w6: J4.54@3088.2,2420.74 3088.2,2335.38 v2(3103.95,2319.63) ; v1(5618.5,1207.24) 5657.5,1168.24 5657.5,1051.87 5670,1039.37 v1(5670,974.37) ; U36.3@5670,922.79 5670,882.97 5683.6,869.37 5706.4,869.37 5720,882.97 U36.2@5720,922.79
  TOP w6.8: U36.3@5670,922.79 v1(5670,974.37)
  ART03 w6: v1(3023,1639) 3052.67,1639 3068,1654.33 3119.67,1654.33 3136,1638 3163,1638 3173,1628 3314,1628 3357.33,1671.33 4549.67,1671.33 4575,1646 5606.5,1646 5618.5,1634 v1(5618.5,1207.24)
  ART04 w6: v1(3023,1639) 3087.45,1703.45 3087.45,2303.13 v2(3103.95,2319.63)
  BOTTOM w6.8: R289.1@5668.5,1014.37 5668.5,975.87 v1(5670,974.37)
RS485_1_RX: J30.5 U36.1 | length 1563.3
  TOP w6.8: U36.1@5770,922.79 v1(5770,974.37)
  ART03 w6: J30.5@4385,915 4441,971 4502,971 4523.21,992.21 v1(4629.68,992.21)
  BOTTOM w6.8: v1(4629.68,992.21) 4672.89,949 5174,949 5262,1037 5459,1037 5486.63,1009.37 5609.61,1009.37 5662.01,956.97 5752.6,956.97 v1(5770,974.37)
RS485_1_TX: J30.6 U36.4 | length 1263.7
  TOP w6: U36.4@5620,922.79 v1(5620,974.37)
  ART03 w6: J30.6@4485,915 4522.84,952.84 v1(4629.68,952.84)
  BOTTOM w6.8: v1(4629.68,952.84) 4651.52,931 5186,931 5271,1016 5454,1016 5475.63,994.37 5600,994.37 v1(5620,974.37)
RS485_2_3V3: C243.1 D60.2 L23.2 U19.8 | length 238.7
  TOP w12: U19.8@5465,725.95 v1(5465,774.37)
  BOTTOM w10: D60.2@5402.95,729.37 5450,729.37 5465,744.37 v1(5465,774.37) C243.1@5465,804.69 5431.18,804.69 L23.2@5411.5,824.37
RS485_2_A: DN1.1 J22.4 R293.1 R294.2 U19.6 | length 1790
  TOP w8: J22.4@4319.37,238.19 4373.4,238.19 4385.8,225.79 4385.8,149.78 4407.77,127.8 4517.24,127.8 4530.49,127.8 4560,157.31 4560,337.37 4583.63,361 4801.63,361 4988.13,547.5 DN1.1@4993.5,547.5 5021,575 5049.63,575 5075,600.37 5075,647.37 5091,663.37 5177.46,663.37 5190.71,663.37 5200.09,672.74 5213.69,686.34 5213.69,805.27 5226.58,818.17 5246.52,818.17 R294.2@5255,809.69 ; R293.1@5255,764.05 R294.2@5255,809.69 ; U19.6@5365,725.95 5365,767.37 5382,784.37 5382,806.37 5366,822.37 5267.68,822.37 R294.2@5255,809.69
RS485_2_B: DN1.2 J22.3 R294.1 R296.1 U19.7 | length 1844.5
  TOP w8: J22.3@4469.37,238.19 4417.82,238.19 4401.8,222.17 4401.8,156.4 4414.4,143.8 4523.87,143.8 4544,163.94 4544,344 4577,377 4795,377 4960,542 4960,589 DN1.2@4993.5,622.5 5025,591 5043,591 5059,607 5059,654 5084.37,679.37 5184.09,679.37 5197.69,692.97 5197.69,811.9 5219.95,834.17 5240.12,834.17 R294.1@5255,849.05 ; R296.1@5255,894.69 R294.1@5255,849.05 ; U19.7@5415,725.95 5415,766.37 5398,783.37 5398,813 5372.63,838.37 5265.68,838.37 R294.1@5255,849.05
RS485_2_DIR: J4.56 R295.1 U19.2 U19.3 | length 4790.3
  TOP w6: v2(3103.95,2392) J4.56@3103.95,2420.74 ; v1(5365,975) U19.3@5365,922.79 5365,882.97 5378.6,869.37 5401.4,869.37 5415,882.97 U19.2@5415,922.79
  ART03 w6: v1(3056.07,1008) 3979,1008 4022,965 4264.1,965 4359.1,870 4625.58,870 v1(4629.68,874.1)
  BOTTOM w6: v1(3056.07,1008) 3055.07,1007 2938,1007 2926,1019 2926,1057 2914,1069 2731,1069 2719,1081 2719,1390 2737,1408 2984,1408 3004,1428 3004,1856 2984,1876 2984,2280 2996,2292 3108,2292 3120,2304 3120,2376.56 3104.56,2392 v2(3103.95,2392) ; R295.1@5348.5,924.37 5348.5,958.5 v1(5365,975)
  BOTTOM w6.8: v1(4629.68,874.1) 4644.15,888.57 5229.2,888.57 5315.63,975 v1(5365,975)
RS485_2_RX: J31.5 U19.1 | length 1537.7
  TOP w6: U19.1@5465,922.79 v1(5465,974.37)
  ART03 w6: J31.5@4140,915 4200,855 4646,855 4652,861 4652,896.15 4634.68,913.47 v1(4629.68,913.47)
  BOTTOM w6.8: v1(4629.68,913.47) 4633.15,910 5221,910 5308,997 5442.37,997 v1(5465,974.37)
RS485_2_TX: J31.6 U19.4 | length 1885.1
  TOP w6: v1(4629.68,1119.69) 4650,1099.37 4650,1005 4675,980 5085,980 5110,1005 5303,1005 5315,993 U19.4@5315,922.79
  BOTTOM w6: J31.6@4240,915 4190,965 4190,1045 4170,1065 4105,1065 4090,1080 4090,1193 4102,1205 4617.68,1205 4629.68,1193 v1(4629.68,1119.69)
RST: C15.1 D4.2 R5.1 SW3.2 | length 276
  TOP w6: SW3.2@664.14,178.81 713.82,178.81 724.68,189.68 D4.2@724.68,310 C15.1@724.68,350 R5.1@775.32,350
RTC_32K_IN: J2.50 R277.2 | length 2359.7
  TOP w6: v2(3056.7,420.89) J2.50@3056.7,465.62
  ART03 w6: v1(3056.7,1050.7) 3084,1078 4024.21,1078 4093.21,1147 4563,1147 v1(4629.68,1080.32)
  ART04 w6: v2(3056.7,420.89) 3056.7,850.7 3074,868 3074,1033.4 v1(3056.7,1050.7)
  BOTTOM w6: v1(4629.68,1080.32) R277.2@4660,1080.32
RTC_INT: J2.48 R3.2 U35.3 | length 2599.7
  TOP w6: v2(3025.2,387.89) 3040.95,403.63 J2.48@3040.95,465.62 ; U35.3@4742.8,1018.39 v1(4742.8,1050.2)
  ART03 w6: v1(3003,1048) 3022.31,1028.69 4034.69,1028.69 4060,1054 4576,1054 4606.05,1023.95 4718.95,1023.95 4742.8,1047.8 v1(4742.8,1050.2)
  ART04 w6: v1(3003,1048) 3003,410.09 v2(3025.2,387.89)
  BOTTOM w6: R3.2@4740,1080.32 4740,1053 v1(4742.8,1050.2)
S0: R226.2 U26.2 | length 101.4
  TOP w6: U26.2@4493.11,1475.43 4533,1475.43 4545,1487.43 v1(4545,1500)
  BOTTOM w6: R226.2@4515,1495.32 4540.32,1495.32 v1(4545,1500)
S1: R225.2 U26.3 | length 78.4
  TOP w6: v1(4446.02,1501.02) U26.3@4493.11,1501.02
  BOTTOM w6: v1(4446.02,1501.02) 4451.73,1495.32 R225.2@4475,1495.32
S2: R233.1 U26.4 | length 110.6
  TOP w6: U26.4@4493.11,1526.61 4558.08,1526.61 R233.1@4590.32,1494.37
SARADC_IN0_BOOT: J3.52 R1.2 | length 3092.5
  TOP w6: v1(994.68,349.68) R1.2@1020,349.68 ; v2(2065.85,2392) J3.52@2065.85,2420.74
  ART03 w6: v1(1460,2298.74) 1570.74,2298.74 1596,2324 2028,2324 2049.36,2345.36 2049.36,2375.5 v2(2065.85,2392)
  BOTTOM w6: v1(994.68,349.68) 1016,371 1364,371 1399,406 1399,443 1412,456 1412,1548 1390,1570 1390,2031.13 1375,2046.13 1375,2199 1394,2218 1394,2232.74 v1(1460,2298.74)
SARADC_IN3: J3.48 R336.2 R337.1 | length 633.4
  TOP w6: R336.2@1505,2284.68 R337.1@1555,2284.68 1571.32,2301 1648,2301 1662,2315 2010,2315 2019,2324 2019,2369 2034.36,2384.36 J3.48@2034.36,2420.74
SARADC_IN5: J3.44 R338.1 | length 3349.7
  TOP w6: v2(2002.86,2392) J3.44@2002.86,2420.74
  ART03 w6: v1(1460,2180.63) 1496,2180.63 1508,2192.63 1508,2266 1520,2278 1579,2278 1603,2302 2032,2302 2081,2351 2081,2401 2069,2413 2023.86,2413 v2(2002.86,2392)
  BOTTOM w6: v1(1460,2180.63) 1460,1604 1479,1585 1479,390 1499,370 1599,370 1610,359 2058.32,359 2070.32,347 R338.1@2070.32,310
SARADC_IN6: J3.42 R339.1 | length 3194.9
  TOP w6: v2(1971.36,2359) 1987.11,2374.75 J3.42@1987.11,2420.74
  ART03 w6: v1(1460,2220) 1478.75,2238.75 1478.75,2270.25 1470.26,2278.74 1449,2278.74 1437,2290.74 1437,2308 1449,2320 1560,2320 1584,2344 1956.36,2344 v2(1971.36,2359)
  BOTTOM w6: v1(1460,2220) 1440,2200 1440,1592 1458,1574 1458,344 1476,326 1604,326 1613,335 1965.32,335 R339.1@1990.32,310
SARADC_IN7: J3.40 R340.1 | length 3182.1
  TOP w6: v2(1971.36,2392) J3.40@1971.36,2420.74
  ART03 w6: v1(1460,2259.37) 1427,2259.37 1415,2271.37 1415,2329 1427,2341 1547,2341 1570,2364 1692,2364 1704,2376 1955.36,2376 v2(1971.36,2392)
  BOTTOM w6: v1(1460,2259.37) 1417,2216.37 1417,1577 1437,1557 1437,315 1463,289 1595,289 1616,310 R340.1@1910.32,310
SATA30_0_RXN: C297.1 J2.6 | length 159.7
  TOP w6.5: C297.1@2675,344.68 2660.75,358.93 2660.75,387.27 2673.75,400.27 2694.88,400.27 2708.12,413.51 2708.12,429.16 2710.24,431.28 J2.6@2710.24,465.62
SATA30_0_RXP: C298.1 J2.4 | length 159.7
  TOP w6.5: C298.1@2635,344.68 2649.25,358.93 2649.25,392.04 2668.99,411.77 2690.12,411.77 2696.62,418.27 2696.62,429.16 2694.49,431.28 J2.4@2694.49,465.62
SATA30_0_TXN: C296.1 J2.10 | length 128.2
  TOP w6.5: J2.10@2741.74,465.62 2741.74,431.28 2739.61,429.16 2739.61,360.07 C296.1@2755,344.68
SATA30_0_TXP: C295.1 J2.8 | length 127.3
  TOP w6.5: C295.1@2715,344.68 2728.11,357.79 2728.11,429.16 2725.99,431.28 J2.8@2725.99,465.62
SATA_5V0: C290.2 C291.1 C292.1 J38.1 L26.2 R316.2 | length 1854.4
  TOP w6.8: v1(1049.5,1092.87) C291.1@1085,1092.87
  TOP w30: v1(1203.42,310.63) 1213,301.05 1213,136 1247.63,101.37 2352.03,101.37 J38.1@2409.72,159.06
  ART03 w6: v1(1049.5,1053.5) v1(1049.5,1092.87)
  BOTTOM w6: C290.2@749.68,1119.37 R316.2@749.68,1079.37 749.68,1059.32 760,1049 1045,1049 v1(1049.5,1053.5)
  other v1: 1164.05,310.63 1242.79,310.63 1164.05,350 1203.42,350 1242.79,350 1088.87,1053.5 1128.24,1053.5 1128.24,1092.87
SATA_12V: C280.1 C281.1 C282.1 J38.4 Q5.3 | length 1608
  BOTTOM w30: 1170,67.37 2669.72,67.37 2709.72,107.37 J38.4@2709.72,159.06
  other v1: 463.26,58.48 502.63,58.48 542,58.48 463.26,97.85 502.63,97.85 542,97.85
SATA_PWR_EN: J2.69 R318.2 R320.1 | length 4338.8
  TOP w6: R320.1@480,799.05 480,828.89 v1(485.87,834.76) ; J2.69@3214.18,569.96 3214.18,629.18 3230,645 v2(3230,792)
  ART03 w6: v1(1299.37,871) 1316.37,888 2226,888 2308,806 3216,806 v2(3230,792)
  BOTTOM w6: R318.2@630.32,1079.37 630.32,1040.69 617,1027.37 512,1027.37 503.27,1018.64 503.27,852.16 v1(485.87,834.76) 485.87,689.97 499.47,676.37 530,676.37 559,647.37 559,473 577,455 1019,455 1057,417 1316,417 1376,477 1376,842 1347,871 v1(1299.37,871)
SATA_RXN: C297.2 D86.2 J39.5 | length 779.1
  TOP w6.5: v1(2670.08,260.11) 2660.75,269.44 2660.75,291.07 C297.2@2675,305.32
  BOTTOM w6.5: v1(2670.08,260.11) 2659.75,249.78 2659.75,232.5 2666.25,226 2923.74,226 3038.34,340.6 3081.01,340.6 3100.75,320.87 3100.75,297.72 3115.32,283.15 D86.2@3115.32,265 3101.73,251.41 3101.73,166.89 J39.5@3120.98,147.64
SATA_RXP: C298.2 D85.2 J39.6 | length 780.7
  TOP w6.5: C298.2@2635,305.32 2649.25,291.07 2649.25,271.44 v1(2637.92,260.11)
  BOTTOM w6.5: v1(2637.92,260.11) 2648.25,249.78 2648.25,227.74 2661.49,214.5 2928.5,214.5 3043.1,329.1 3076.25,329.1 3089.25,316.1 3089.25,297.72 3074.68,283.15 D85.2@3074.68,265 3090.23,249.45 3090.23,166.89 J39.6@3070.98,147.64
SATA_TXN: C296.2 D87.2 J39.3 | length 928.3
  TOP w6.5: C296.2@2755,305.32 2740.75,291.07 2740.75,266.04 2747.25,259.54 2932.67,259.54 ccw(c2932.67,266.27) 2939.4,266.27 cw(c2946.13,266.27) 2946.13,273 2958.67,273 cw(c2958.67,266.27) 2965.4,266.27 ccw(c2972.13,266.27) 2972.13,259.54 2984.67,259.54 ccw(c2984.67,266.27) 2991.4,266.27 cw(c2998.13,266.27) 2998.13,273 3010.67,273 cw(c3010.67,266.27) 3017.4,266.27 ccw(c3024.13,266.27) 3024.13,259.54 3036.67,259.54 ccw(c3036.67,266.27) 3043.4,266.27 cw(c3050.13,266.27) 3050.13,273 3062.67,273 cw(c3062.67,266.27) 3069.4,266.27 ccw(c3076.13,266.27) 3076.13,259.54 3088.67,259.54 ccw(c3088.67,266.27) 3095.4,266.27 cw(c3102.13,266.27) 3102.13,273 3114.67,273 cw(c3114.67,266.27) 3121.4,266.27 ccw(c3128.13,266.27) 3128.13,259.54 3140.67,259.54 ccw(c3140.67,266.27) 3147.4,266.27 cw(c3154.13,266.27) 3154.13,273 3166.67,273 cw(c3166.67,266.27) 3173.4,266.27 ccw(c3180.13,266.27) 3180.13,259.54 3196.43,259.54 3211,274.11 3211,306.74 3203.24,314.5 3188.62,314.5 v1(3178.29,304.17)
  BOTTOM w6.5: v1(3178.29,304.17) 3188.62,314.5 3229.75,314.5 3249.25,295 3249.25,279.57 D87.2@3234.68,265 3249.25,250.43 3249.25,209.78 3240.23,200.76 3240.23,166.89 J39.3@3220.98,147.64
SATA_TXP: C295.2 D88.2 J39.2 | length 927.7
  TOP w6.5: C295.2@2715,305.32 2729.25,291.07 2729.25,261.27 2742.49,248.04 3201.2,248.04 3222.5,269.34 3222.5,311.5 3208,326 3188.62,326 v1(3178.29,336.33)
  BOTTOM w6.5: v1(3178.29,336.33) 3188.62,326 3234.51,326 3260.75,299.76 3260.75,279.57 D88.2@3275.32,265 3260.75,250.43 3260.75,205.02 3251.73,196 3251.73,166.89 J39.2@3270.98,147.64
SD_CD: D16.2 J24.9 R283.2 | length 227.2
  TOP w6.8: R283.2@6034.68,355 6059.68,330 6109.68,330 D16.2@6134.68,355 6137.43,357.75 J24.9@6240.06,357.75
SD_CLK: D19.2 J24.5 R280.2 | length 236.8
  TOP w6.8: R280.2@6034.68,505 6059.68,480 6109.68,480 D19.2@6134.68,505 6160.66,530.98 J24.5@6240.06,530.98
SD_CMD: D20.2 J24.3 R279.2 | length 228.4
  TOP w6.8: R279.2@6034.68,610 6058.68,586 6110.68,586 D20.2@6134.68,610 6142.28,617.6 J24.3@6240.06,617.6
SD_DAT0: D18.2 J24.7 R281.2 | length 230.5
  TOP w6.8: R281.2@6034.68,455 6059.68,430 6109.68,430 D18.2@6134.68,455 6145.31,444.37 J24.7@6240.06,444.37
SD_DAT1: D17.2 J24.8 R282.2 | length 227.7
  TOP w6.8: R282.2@6034.68,405 6059.68,380 6109.68,380 D17.2@6134.68,405 6138.62,401.06 J24.8@6240.06,401.06
SD_DAT2: D22.2 J24.1 R275.2 | length 227.7
  TOP w6.8: R275.2@6034.68,710 6058.68,686 6110.68,686 D22.2@6134.68,710 6140.47,704.21 J24.1@6240.06,704.21
SD_DAT3: D21.2 J24.2 R278.2 | length 226.5
  TOP w6.8: R278.2@6034.68,660 6059.68,635 6109.68,635 D21.2@6134.68,660 6135.58,660.9 J24.2@6240.06,660.9
SDMMC_CLK: J4.77 R280.1 | length 4582
  TOP w6.8: v2(3261.43,2225.14) 3277.18,2240.89 J4.77@3277.18,2286.88 ; v1(5965,505) R280.1@5995.32,505
  ART04 w6.3: v2(3261.43,2225.14) 3261.43,2200.43 3252.4,2191.4 3252.4,1913.52 3423.85,1742.07 3810.8,1742.07 3829.82,1723.05 4120.98,1723.05 4140,1742.07 4459.07,1742.07 4511,1794 5597.38,1794 6039,1352.38 6039,833.65 6046.38,826.27 6080.62,826.27 6088,818.89 6088,647.37 6067,626.37 6046,626.37 6017,597.37 5910.6,597.37 5900.3,587.07 5900.3,541.67 5912.6,529.37 5952.4,529.37 5965,516.77 v1(5965,505)
SDMMC_CMD: J4.79 R279.1 | length 4604.8
  TOP w6.8: v2(3292.92,2258.14) J4.79@3292.92,2286.88 ; v1(5925.63,560) 5925.63,596.4 5939.23,610 R279.1@5995.32,610
  ART04 w6.3: v2(3292.92,2258.14) 3276.58,2241.8 3276.58,1918.05 3426.93,1767.7 4455.7,1767.7 4506,1818 5602.09,1818 6062,1358.09 6062,915.63 6069.38,908.25 6091.62,908.25 6099,900.87 6099,890.43 6091.62,883.05 6069.38,883.05 6062,875.67 6062,864.37 6070.93,855.45 6101.62,855.45 6109,848.06 6109,589.37 6095,575.37 5941,575.37 v1(5925.63,560)
SDMMC_D0: J4.69 R281.1 | length 4619.9
  TOP w6.8: v2(3198.43,2225.14) 3214.18,2240.89 J4.69@3214.18,2286.88 ; v1(5900,455) R281.1@5995.32,455
  ART04 w6.3: v2(3198.43,2225.14) 3208.3,2215.28 3208.3,1895.25 3402.08,1701.47 3793.98,1701.47 3813,1682.45 4152.07,1682.45 4171.09,1701.47 4480.47,1701.47 4526,1747 5448,1747 5473,1722 5605,1722 5995.3,1331.7 5995.3,652.27 5982.7,639.67 5863.53,639.67 5850.63,626.77 5850.63,467.6 5863.23,455 v1(5900,455)
SDMMC_D1: J4.71 R282.1 | length 4632.1
  TOP w6.8: v2(3229.93,2258.14) J4.71@3229.93,2286.88 ; v1(5965,405) R282.1@5995.32,405
  ART04 w6.3: v2(3229.93,2258.14) 3245.08,2242.99 3245.08,2210.08 3232.1,2197.1 3232.1,1905.11 3415.44,1721.77 3802.39,1721.77 3821.41,1702.75 4139.98,1702.75 4159,1721.77 4467.77,1721.77 4518,1772 5590.67,1772 6018,1344.67 6018,632.37 6005,619.37 5892.6,619.37 5880,606.77 5880,496.97 5892.6,484.37 5952.4,484.37 5965,471.77 v1(5965,405)
SDMMC_D2: J4.73 R275.1 | length 4638.4
  TOP w6.8: v2(3229.93,2225.14) 3245.68,2240.89 J4.73@3245.68,2286.88 ; v1(5966,710) R275.1@5995.32,710
  ART04 w6.3: v2(3229.93,2225.14) 3215.18,2239.89 3192.32,2239.89 3183.68,2231.25 3183.68,2202.32 3188,2198 3188,1886.85 3397.18,1677.67 3777.33,1677.67 3792.85,1662.15 4160.48,1662.15 4176,1677.67 4492.67,1677.67 4531,1716 5305,1716 5321,1700 5577.37,1700 5834,1443.37 5834,1333.88 5840.3,1327.58 5932.62,1327.58 5940,1320.2 5940,1309.76 5931.62,1301.38 5836.38,1301.38 5829,1294 5829,1283.56 5836.38,1276.18 5933.62,1276.18 5940,1269.8 5940,1259.36 5931.62,1250.98 5836.38,1250.98 5829,1243.6 5829,1232.3 5835.3,1226 5954.4,1226 5966,1214.4 v1(5966,710)
SDMMC_D3: J4.75 R278.1 | length 4549.6
  TOP w6.8: v2(3261.43,2258.14) J4.75@3261.43,2286.88 ; v1(5966,660) R278.1@5995.32,660
  ART04 w6.3: v2(3261.43,2258.14) 3242.57,2277 3164.37,2277 3151,2263.63 3151,2183.7 3167.7,2167 3167.7,1785.3 3295.63,1657.37 3750.63,1657.37 3787,1621 4152.63,1621 4189,1657.37 4504.37,1657.37 4542.7,1695.7 5034.3,1695.7 5052.91,1677.09 5563.27,1677.09 5802,1438.37 5802,1209.3 5810.3,1201 5922.4,1201 5935,1188.4 5935,1177.1 5927.62,1169.72 5868.38,1169.72 5861,1162.34 5861,1151.9 5868.38,1144.52 5927.62,1144.52 5935,1137.14 5935,691 v1(5966,660)
SDMMC_DET: J4.81 R283.1 R284.2 | length 4654.5
  TOP w6: v2(3292.92,2225.14) 3308.67,2240.89 J4.81@3308.67,2286.88 ; R284.2@5939.68,355 v1(5965,355) R283.1@5995.32,355
  ART04 w6: v2(3292.92,2225.14) 3302,2216.07 3302,1921.34
  ART04 w6.3: 3302,1921.34 3435.34,1788 4442,1788 4493,1839 5609.79,1839 6089,1359.79 6089,960 6133,916 6133,549.97 6120.4,537.37 6003.37,537.37 5988,522 5988,378 v1(5965,355)
SIM_CLK0: J23.12 R259.1 | length 1737.9
  TOP w6: J23.12@5515.75,2239.43 5515.75,2076.25 5590.5,2001.51 5590.5,1325.51 5617.14,1298.87 5813.05,1298.87 5836,1275.91 5836,816 v1(5810,790)
  BOTTOM w6.8: v1(5810,790) R259.1@5840.32,790
SIM_DATA0: J23.10 R260.1 | length 1776.2
  TOP w6: J23.10@5547.25,2239.43 5547.25,2084.75 5621.99,2010.01 5621.99,1356.01 5647.64,1330.36 5826.09,1330.36 5856,1300.46 5856,791 v1(5810,745)
  BOTTOM w6.8: v1(5810,745) R260.1@5840.32,745
SIM_RST0: J23.14 R258.1 | length 1691.3
  TOP w6: J23.14@5484.25,2239.43 5484.25,2068.75 5559,1994 5559,1305 5596.63,1267.37 5800,1267.37 5813,1254.37 5813,838 v1(5810,835)
  BOTTOM w6.8: v1(5810,835) R258.1@5840.32,835
SIM_VDD: J21.1 J23.8 R253.1 U30.6 | length 2592.6
  TOP w10: J23.8@5578.74,2239.43 5578.74,2093.26 5653.49,2018.51 5653.49,1381.86 5673.49,1361.86 5915,1361.86 5935,1341.86 5935,815 5955,795 ; v1(5810,700) 5878,768 5928,768 5955,795 ; v1(6069.69,795) 5955,795 ; v1(6187,795) v1(6305,795)
  BOTTOM w10: v1(5810,700) R253.1@5840.32,700 ; v1(6069.69,795) U30.6@6069.69,821.58 6118.43,821.58 6145,795 v1(6187,795) ; J21.1@6218.9,620.79 6285,620.79 6305,640.79 v1(6305,795)
SPK_CTRL: J4.58 R345.1 R351.1 | length 3469
  TOP w6: R345.1@999.68,2445 1025,2445 v1(1030,2450) ; v1(1425.32,2400.32) R351.1@1455,2400.32 1455,2381 1467,2369 1573,2369 1585,2381 1585,2444 1607.38,2466.38 v1(2063.21,2466.38) ; v2(3103.95,2359) 3119.7,2374.75 J4.58@3119.7,2420.74
  ART03 w6: v1(1030,2450) 1297,2450 1314,2433 1392.64,2433 v1(1425.32,2400.32)
  ART04 w6: v1(2063.21,2466.38) 2101,2428.59 2101,1864 2144,1821 2895,1821 2932,1858 2932,2333 2954,2355 2954,2402 2966,2414 3048.95,2414 v2(3103.95,2359)
SPK_LN: C301.1 J42.1 L19.2 | length 227.8
  TOP w15: J42.1@1069.37,3137.49 1069.37,3005.95 C301.1@1100.32,2975 1110,2965.32 L19.2@1110,2926.5
SPK_LP: C300.1 J42.2 L27.2 | length 223.7
  TOP w15: L27.2@960,2926.5 960,2970.32 C300.1@964.68,2975 990.63,3000.95 J42.2@990.63,3137.49
SPK_RN: C311.1 J43.1 L28.2 | length 228.1
  TOP w15: J43.1@1513.78,3137.49 1513.78,3006.54 C311.1@1545.32,2975 1555,2965.32 L28.2@1555,2926.5
SPK_RP: C310.1 J43.2 L29.2 | length 223.4
  TOP w15: L29.2@1405,2926.5 1405,2965.32 C310.1@1414.68,2975 1435.04,2995.36 J43.2@1435.04,3137.49
SYS_LED: J2.65 R334.1 | length 7890.3
  TOP w6: v1(3174.81,1356.63) 3174.81,883.19 3193,865 3193,662 3182.68,651.68 J2.65@3182.68,569.96 ; R334.1@5935.32,3539.37 5935.32,3503.97 5948.92,3490.37 6557,3490.37 6587,3460.37 6587,3054.97 6600.6,3041.37 6689.4,3041.37 6703,3027.77 6703,1099.97 6689.4,1086.37 6221,1086.37 6209,1098.37 v1(6209,1373)
  ART03 w6: v1(3174.81,1356.63) 3251.44,1280 4276,1280 4369,1373 4469.89,1373 v1(4521.26,1424.37)
  BOTTOM w6: v1(4521.26,1424.37) 4544.86,1400.77 5133.23,1400.77 5157.63,1376.37 6205.63,1376.37 v1(6209,1373)
TYPEC0_SBU1: C84.2 J3.84 | length 2850.4
  TOP w5.2: v2(2309.99,2463.48) 2320.99,2452.48 2320.99,2443.87 2317.82,2440.7 J3.84@2317.82,2420.74
  ART03 w4.5: v1(1490.33,3205) 1480,3194.67 1480,3123 1512,3091 1512,3052 1576,2988 1665,2988 1690,2963 1774,2963 1818,3007 2351,3007 2374,2984 2503,2984 2522.5,2964.5 2522.5,2414.06 2484.44,2376 2357.56,2376 2319.94,2413.62 2319.94,2453.53 v2(2309.99,2463.48)
  BOTTOM w5.2: C84.2@915,3284.69 899.7,3269.39 899.7,3228.59 921.89,3206.4 1178.4,3206.4 1221.89,3249.89 1464.04,3249.89 1479.95,3233.98 1479.95,3215.38 v1(1490.33,3205)
TYPEC0_SBU1_DC: J4.93 R92.2 | length 3855.3
  TOP w6: v2(3387.41,2225.14) 3403.16,2240.89 J4.93@3403.16,2286.88
  ART04 w6: v1(954.68,3277) 976.68,3299 1064,3299 1110,3253 1989,3253 2012,3230 2012,3155 2045,3122 2045,3017 2033,3005 1987,3005 1975,2993 1975,2910 1950,2885 1950,2627 1962,2615 2022,2615 2067,2570 3167,2570 3179,2558 3179,2462 3191,2450 3267,2450 3279,2438 3279,2400 3291,2388 3382,2388 3395,2375 3461,2375 3474,2362 3474,2249 3467,2242 3404.27,2242 v2(3387.41,2225.14)
  BOTTOM w6.8: v1(954.68,3277) R92.2@954.68,3364.37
